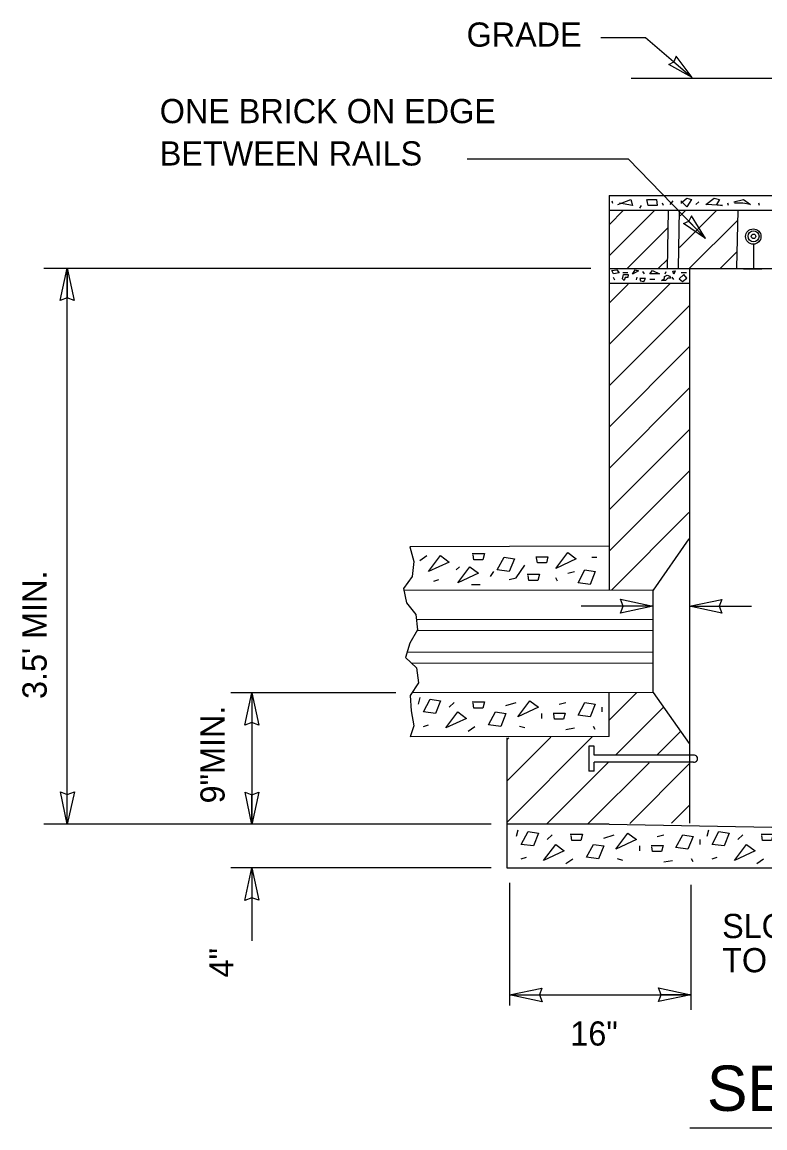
# Model space of a CAD drawing. Extents: x 19188 to 19495, y 20866 to 21061.
# Drawn here: x 19190.86 to 19216.59, y 20978.71 to 21017 of the extents above; entities that cross this region are included whole.
import ezdxf

# ---------------------------------------------------------------- set-up
doc = ezdxf.new("R2010")
doc.units = 0
doc.layers.add('G-ANNO-NOTE', color=7, linetype='Continuous')

msp = doc.modelspace()

# ---------------------------------------------------------------- linework, layer by layer
at = {"layer": 'G-ANNO-NOTE'}
for p, q in [((19220.92, 21015.045), (19211.963, 21015.045)), ((19211.192, 21010.995), (19211.192, 20997.329)), ((19211.192, 21010.995), (19217.267, 21010.995)), ((19211.192, 21010.489), (19242.647, 21010.489)), ((19211.192, 21008.907), (19212.774, 21010.489)), ((19211.192, 21009.981), (19211.699, 21010.489)), ((19213.217, 21008.464), (19213.257, 21010.48)), ((19213.598, 21008.492), (19213.637, 21010.482)), ((19214.921, 21010.489), (19213.63, 21009.197)), ((19213.848, 21010.489), (19213.651, 21010.292)), ((19215.623, 21008.493), (19215.663, 21010.476)), ((19211.823, 21008.464), (19213.233, 21009.874)), ((19213.97, 21008.464), (19215.65, 21010.143)), ((19216.198, 21009.31), (19216.198, 21008.487)), ((19212.896, 21008.464), (19213.224, 21008.792)), ((19215.044, 21008.464), (19215.621, 21009.04)), ((19210.566, 21008.464), (19191.621, 21008.464)), ((19192.426, 20989.226), (19192.426, 21008.477)), ((19192.426, 21008.477), (19192.426, 21007.446)), ((19211.192, 21008.464), (19242.647, 21008.464)), ((19211.293, 21008.401), (19211.465, 21008.418)), ((19211.344, 21008.286), (19211.293, 21008.401)), ((19211.546, 21008.319), (19211.344, 21008.286)), ((19211.465, 21008.418), (19211.546, 21008.319)), ((19211.668, 21008.332), (19211.846, 21008.332)), ((19212.003, 21008.269), (19212.095, 21008.418)), ((19212.216, 21008.385), (19212.003, 21008.269)), ((19212.095, 21008.418), (19212.216, 21008.385)), ((19212.611, 21008.286), (19212.693, 21008.401)), ((19212.693, 21008.401), (19212.946, 21008.286)), ((19213.402, 21008.369), (19213.483, 21008.385)), ((19213.433, 21008.269), (19213.402, 21008.369)), ((19213.483, 21008.385), (19213.433, 21008.269)), ((19213.696, 21008.332), (19213.874, 21008.332)), ((19213.976, 21008.464), (19213.976, 20989.265)), ((19215.848, 21008.459), (19216.485, 21008.459)), ((19211.192, 21007.957), (19213.976, 21007.957)), ((19211.192, 21005.837), (19213.304, 21007.948)), ((19211.192, 21007.269), (19211.852, 21007.928)), ((19211.658, 21008.103), (19211.689, 21008.252)), ((19211.719, 21008.054), (19211.658, 21008.103)), ((19211.689, 21008.252), (19211.851, 21008.252)), ((19211.749, 21008.153), (19211.719, 21008.054)), ((19211.841, 21008.153), (19211.749, 21008.153)), ((19211.851, 21008.252), (19211.841, 21008.153)), ((19212.459, 21008.12), (19212.257, 21008.12)), ((19212.257, 21008.12), (19212.277, 21008.037)), ((19212.277, 21008.037), (19212.399, 21008.02)), ((19212.399, 21008.02), (19212.459, 21008.12)), ((19212.601, 21008.099), (19212.779, 21008.099)), ((19212.946, 21008.286), (19212.611, 21008.286)), ((19213.007, 21008.054), (19213.108, 21008.12)), ((19213.098, 21008.054), (19213.007, 21008.054)), ((19213.149, 21008.054), (19213.098, 21008.054)), ((19213.108, 21008.12), (19213.118, 21008.186)), ((19213.118, 21008.186), (19213.21, 21008.236)), ((19213.23, 21008.136), (19213.149, 21008.054)), ((19213.21, 21008.236), (19213.301, 21008.203)), ((19213.321, 21008.136), (19213.23, 21008.136)), ((19213.301, 21008.203), (19213.321, 21008.136)), ((19213.787, 21008.252), (19213.625, 21008.103)), ((19213.625, 21008.103), (19213.737, 21008.02)), ((19213.737, 21008.02), (19213.889, 21008.136)), ((19213.889, 21008.136), (19213.787, 21008.252)), ((19211.192, 21004.405), (19213.974, 21007.187)), ((19211.192, 21002.973), (19213.972, 21005.753)), ((19211.192, 21001.541), (19213.969, 21004.318)), ((19211.192, 21000.109), (19213.967, 21002.884)), ((19211.192, 20998.677), (19213.964, 21001.449)), ((19211.276, 20997.329), (19213.962, 21000.015)), ((19211.192, 20998.845), (19204.29, 20998.833)), ((19213.96, 20999.103), (19212.718, 20997.329)), ((19204.643, 20998.357), (19204.88, 20998.523)), ((19204.94, 20997.971), (19205.357, 20998.523)), ((19205.357, 20998.523), (19205.654, 20998.302)), ((19207.321, 20998.026), (19207.559, 20998.468)), ((19207.559, 20998.468), (19207.916, 20998.413)), ((19207.916, 20998.413), (19207.737, 20997.971)), ((19209.344, 20998.081), (19209.761, 20998.633)), ((19210.059, 20998.413), (19209.344, 20998.081)), ((19209.761, 20998.633), (19210.059, 20998.413)), ((19210.594, 20998.468), (19210.773, 20998.468)), ((19205.654, 20998.302), (19204.94, 20997.971)), ((19205.892, 20998.026), (19206.011, 20998.136)), ((19205.952, 20997.584), (19206.368, 20998.136)), ((19206.368, 20998.136), (19206.666, 20997.915)), ((19207.082, 20997.805), (19207.202, 20997.971)), ((19207.737, 20997.971), (19207.321, 20998.026)), ((19207.975, 20997.749), (19208.273, 20998.191)), ((19209.761, 20997.915), (19209.999, 20997.971)), ((19210.118, 20997.584), (19210.356, 20998.026)), ((19210.356, 20998.026), (19210.714, 20997.971)), ((19210.714, 20997.971), (19210.535, 20997.529)), ((19205.119, 20997.639), (19205.297, 20997.695)), ((19206.666, 20997.915), (19205.952, 20997.584)), ((19207.737, 20997.695), (19207.975, 20997.749)), ((19209.404, 20997.639), (19209.344, 20997.749)), ((19210.535, 20997.529), (19210.118, 20997.584)), ((19212.718, 20997.329), (19204.109, 20997.314)), ((19206.428, 20997.529), (19206.726, 20997.529)), ((19212.707, 20997.329), (19212.744, 20997.366)), ((19212.711, 20997.329), (19212.711, 20993.785)), ((19212.711, 20996.772), (19210.23, 20996.772)), ((19212.711, 20996.772), (19211.681, 20996.772)), ((19213.976, 20996.772), (19216.126, 20996.772)), ((19213.976, 20996.772), (19215.007, 20996.772)), ((19212.72, 20996.316), (19204.558, 20996.303)), ((19212.693, 20995.936), (19204.559, 20995.923)), ((19212.694, 20995.177), (19204.217, 20995.163)), ((19212.693, 20994.797), (19204.377, 20994.784)), ((19203.809, 20993.771), (19198.097, 20993.771)), ((19198.821, 20993.771), (19198.821, 20989.213)), ((19198.821, 20993.771), (19198.821, 20992.741)), ((19212.725, 20993.785), (19204.379, 20993.771)), ((19211.192, 20992.264), (19211.192, 20993.785)), ((19211.192, 20992.824), (19212.154, 20993.785)), ((19212.725, 20993.785), (19213.972, 20992.015)), ((19204.643, 20993.606), (19204.583, 20993.385)), ((19204.761, 20993.109), (19204.999, 20993.551)), ((19204.999, 20993.551), (19205.357, 20993.496)), ((19205.357, 20993.496), (19205.178, 20993.054)), ((19205.833, 20993.441), (19205.654, 20993.275)), ((19207.618, 20993.33), (19207.975, 20993.441)), ((19208.035, 20992.943), (19208.451, 20993.496)), ((19208.451, 20993.496), (19208.749, 20993.275)), ((19209.463, 20993.385), (19209.701, 20993.441)), ((19210.118, 20992.999), (19210.356, 20993.441)), ((19210.356, 20993.441), (19210.714, 20993.385)), ((19210.714, 20993.385), (19210.535, 20992.943)), ((19205.178, 20993.054), (19204.761, 20993.109)), ((19205.535, 20992.557), (19205.952, 20993.109)), ((19205.952, 20993.109), (19206.25, 20992.888)), ((19207.023, 20992.667), (19207.261, 20993.109)), ((19207.261, 20993.109), (19207.618, 20993.054)), ((19207.618, 20993.054), (19207.44, 20992.612)), ((19208.749, 20993.275), (19208.035, 20992.943)), ((19208.868, 20992.888), (19208.868, 20993.054)), ((19210.535, 20992.943), (19210.118, 20992.999)), ((19210.952, 20993.109), (19210.952, 20993.275)), ((19213.075, 20993.274), (19211.441, 20991.64)), ((19204.761, 20992.612), (19204.94, 20992.667)), ((19206.25, 20992.888), (19205.535, 20992.557)), ((19206.309, 20992.446), (19206.547, 20992.612)), ((19207.44, 20992.612), (19207.023, 20992.667)), ((19208.273, 20992.557), (19208.095, 20992.612)), ((19210.713, 20992.502), (19210.654, 20992.612)), ((19211.192, 20992.264), (19204.301, 20992.252)), ((19207.649, 20989.28), (19210.624, 20992.256)), ((19207.649, 20990.712), (19209.172, 20992.236)), ((19207.649, 20992.144), (19207.72, 20992.215)), ((19207.649, 20992.214), (19207.649, 20989.226)), ((19209.701, 20992.502), (19209.999, 20992.557)), ((19213.67, 20992.438), (19212.869, 20991.637)), ((19210.676, 20991.926), (19210.488, 20991.926)), ((19210.488, 20991.926), (19210.488, 20991.059)), ((19210.676, 20991.619), (19210.676, 20991.926)), ((19214.117, 20991.619), (19210.676, 20991.619)), ((19209.035, 20989.235), (19211.16, 20991.36)), ((19210.475, 20989.244), (19212.581, 20991.349)), ((19214.122, 20991.366), (19210.676, 20991.366)), ((19210.676, 20991.059), (19210.676, 20991.366)), ((19211.916, 20989.252), (19213.973, 20991.309)), ((19210.676, 20991.059), (19210.488, 20991.059)), ((19192.426, 20989.226), (19192.426, 20990.257)), ((19198.821, 20989.213), (19198.821, 20990.244)), ((19213.357, 20989.261), (19213.976, 20989.879)), ((19207.107, 20989.226), (19191.621, 20989.226)), ((19211.192, 20989.226), (19207.649, 20989.226)), ((19207.649, 20989.226), (19207.649, 20987.708)), ((19211.192, 20989.226), (19240.021, 20988.692)), ((19208.035, 20989.021), (19207.975, 20988.8)), ((19208.154, 20988.524), (19208.392, 20988.966)), ((19208.392, 20988.966), (19208.749, 20988.911)), ((19208.749, 20988.911), (19208.571, 20988.469)), ((19209.225, 20988.855), (19209.047, 20988.69)), ((19211.011, 20988.745), (19211.368, 20988.855)), ((19211.428, 20988.358), (19211.844, 20988.911)), ((19211.844, 20988.911), (19212.142, 20988.69)), ((19212.856, 20988.8), (19213.094, 20988.855)), ((19213.511, 20988.413), (19213.749, 20988.855)), ((19213.749, 20988.855), (19214.106, 20988.8)), ((19214.106, 20988.8), (19213.927, 20988.358)), ((19214.642, 20989.021), (19214.582, 20988.8)), ((19214.761, 20988.524), (19214.999, 20988.966)), ((19214.999, 20988.966), (19215.356, 20988.911)), ((19215.356, 20988.911), (19215.177, 20988.469)), ((19215.832, 20988.855), (19215.653, 20988.69)), ((19208.571, 20988.469), (19208.154, 20988.524)), ((19208.927, 20987.971), (19209.344, 20988.524)), ((19209.344, 20988.524), (19209.642, 20988.303)), ((19210.416, 20988.082), (19210.654, 20988.524)), ((19210.654, 20988.524), (19211.011, 20988.469)), ((19211.011, 20988.469), (19210.832, 20988.027)), ((19212.142, 20988.69), (19211.428, 20988.358)), ((19212.261, 20988.303), (19212.261, 20988.469)), ((19213.927, 20988.358), (19213.511, 20988.413)), ((19214.344, 20988.524), (19214.344, 20988.69)), ((19215.177, 20988.469), (19214.761, 20988.524)), ((19215.534, 20987.971), (19215.951, 20988.524)), ((19215.951, 20988.524), (19216.249, 20988.303)), ((19208.154, 20988.027), (19208.333, 20988.082)), ((19209.642, 20988.303), (19208.927, 20987.971)), ((19209.701, 20987.861), (19209.94, 20988.027)), ((19210.832, 20988.027), (19210.416, 20988.082)), ((19211.666, 20987.971), (19211.487, 20988.027)), ((19214.106, 20987.916), (19214.047, 20988.027)), ((19214.761, 20988.027), (19214.939, 20988.082)), ((19216.249, 20988.303), (19215.534, 20987.971)), ((19216.308, 20987.861), (19216.546, 20988.027)), ((19207.107, 20987.708), (19198.097, 20987.708)), ((19198.821, 20987.708), (19198.821, 20985.181)), ((19198.821, 20987.708), (19198.821, 20986.677)), ((19207.649, 20987.708), (19249.414, 20987.708)), ((19213.094, 20987.916), (19213.391, 20987.971)), ((19207.75, 20987.197), (19207.75, 20982.941)), ((19214.025, 20987.123), (19214.025, 20982.792)), ((19207.75, 20983.315), (19214.025, 20983.314)), ((19207.75, 20983.315), (19208.781, 20983.315)), ((19214.025, 20983.314), (19212.995, 20983.314)), ((19213.987, 20978.708), (19246.848, 20978.708))]:
    msp.add_line(p, q, dxfattribs=at)
for points in [[(19210.913, 21016.468), (19212.452, 21016.468), (19214.067, 21015.083)], [(19206.275, 21012.261), (19211.855, 21012.261), (19214.535, 21009.509)], [(19211.292, 21010.811), (19211.318, 21010.726)], [(19211.502, 21010.683), (19211.947, 21010.853), (19212, 21010.641), (19211.555, 21010.726)], [(19212.262, 21010.556), (19212.315, 21010.641)], [(19212.524, 21010.853), (19212.839, 21010.853), (19212.865, 21010.641), (19212.55, 21010.641), (19212.498, 21010.853)], [(19213.075, 21010.641), (19213.049, 21010.726)], [(19213.31, 21010.683), (19213.416, 21010.811)], [(19213.678, 21010.726), (19213.887, 21010.896), (19214.045, 21010.853), (19213.887, 21010.598), (19213.678, 21010.811)], [(19214.202, 21010.683), (19214.307, 21010.768)], [(19214.543, 21010.683), (19214.831, 21010.896), (19215.015, 21010.853), (19214.91, 21010.683), (19215.119, 21010.641), (19214.569, 21010.683)], [(19215.329, 21010.641), (19215.303, 21010.726)], [(19215.513, 21010.768), (19215.854, 21010.853), (19216.09, 21010.683), (19215.827, 21010.726), (19215.539, 21010.726)], [(19216.404, 21010.641), (19216.378, 21010.726)], [(19192.426, 21007.446), (19192.18, 21007.356), (19192.426, 21008.477), (19192.661, 21007.358), (19192.426, 21007.446)], [(19212.419, 21008.279), (19212.367, 21008.364)], [(19213.142, 21008.275), (19213.168, 21008.36)], [(19211.395, 21008.063), (19211.343, 21008.148)], [(19212.139, 21008.076), (19212.165, 21008.162)], [(19213.433, 21008.08), (19213.381, 21008.165)], [(19204.29, 20998.833), (19204.433, 20998.323), (19204.379, 20997.797), (19204.074, 20997.388), (19204.182, 20996.891), (19204.505, 20996.481), (19204.559, 20995.955), (19204.289, 20995.488), (19204.146, 20994.991), (19204.523, 20994.64), (19204.595, 20994.114), (19204.307, 20993.676), (19204.343, 20993.15), (19204.433, 20992.624), (19204.301, 20992.252)], [(19206.456, 20998.595), (19206.875, 20998.595), (19206.823, 20998.383), (19206.509, 20998.383), (19206.483, 20998.553)], [(19208.658, 20998.485), (19209.078, 20998.485), (19209.026, 20998.272), (19208.711, 20998.272), (19208.684, 20998.442)], [(19208.361, 20997.877), (19208.78, 20997.877), (19208.728, 20997.664), (19208.414, 20997.664), (19208.387, 20997.835)], [(19211.68, 20996.772), (19211.59, 20997.018), (19212.711, 20996.772), (19211.592, 20996.536), (19211.68, 20996.772)], [(19215.007, 20996.772), (19215.098, 20996.525), (19213.976, 20996.772), (19215.095, 20997.007), (19215.007, 20996.772)], [(19198.821, 20992.74), (19198.575, 20992.65), (19198.821, 20993.771), (19199.057, 20992.652), (19198.821, 20992.74)], [(19206.456, 20993.458), (19206.875, 20993.458), (19206.823, 20993.245), (19206.509, 20993.245), (19206.483, 20993.416)], [(19209.254, 20993.071), (19209.673, 20993.071), (19209.62, 20992.858), (19209.306, 20992.858), (19209.28, 20993.029)], [(19192.426, 20990.257), (19192.672, 20990.347), (19192.426, 20989.226), (19192.191, 20990.345), (19192.426, 20990.257)], [(19198.821, 20990.244), (19199.068, 20990.334), (19198.821, 20989.213), (19198.586, 20990.332), (19198.821, 20990.244)], [(19209.849, 20988.873), (19210.268, 20988.873), (19210.216, 20988.66), (19209.901, 20988.66), (19209.875, 20988.83)], [(19216.456, 20988.873), (19216.875, 20988.873), (19216.822, 20988.66), (19216.508, 20988.66), (19216.482, 20988.83)], [(19212.646, 20988.486), (19213.066, 20988.486), (19213.013, 20988.273), (19212.698, 20988.273), (19212.672, 20988.443)], [(19198.821, 20986.677), (19198.575, 20986.586), (19198.821, 20987.708), (19199.057, 20986.589), (19198.821, 20986.677)], [(19208.781, 20983.315), (19208.872, 20983.068), (19207.75, 20983.315), (19208.869, 20983.55), (19208.781, 20983.315)], [(19212.994, 20983.314), (19212.904, 20983.561), (19214.025, 20983.314), (19212.906, 20983.079), (19212.994, 20983.314)]]:
    msp.add_lwpolyline(points, dxfattribs=at)
for points in [[(19213.514, 21015.817), (19213.441, 21015.62), (19214.067, 21015.083), (19213.265, 21015.523), (19213.441, 21015.62), (19214.067, 21015.083)], [(19214.051, 21010.289), (19213.96, 21010.099), (19214.535, 21009.509), (19213.776, 21010.018), (19213.96, 21010.099), (19214.535, 21009.509)]]:
    msp.add_lwpolyline(points, close=True, dxfattribs=at)
for centre, radius in [((19216.189, 21009.572), 0.266), ((19216.197, 21009.579), 0.19), ((19216.197, 21009.579), 0.0759)]:
    msp.add_circle(centre, radius, dxfattribs=at)
msp.add_arc((19214.13, 20991.493), 0.127, 266.522, 96.1025, dxfattribs=at)

# ---------------------------------------------------------------- texts
for s, height, p in [('GRADE', 0.8379, (19206.259, 21016.146)), ('ONE BRICK ON EDGE', 0.83785, (19195.63, 21013.497)), ('BETWEEN RAILS', 0.83785, (19195.63, 21012.031)), ('SLOPE FLOOR ', 0.83785, (19215.11, 20985.28)), ('TO DRAIN', 0.8379, (19215.11, 20984.097)), ('16"', 0.8379, (19209.852, 20981.558)), ('SECTION TYPE "S" HANDHOLE', 1.57098, (19214.585, 20979.297))]:
    msp.add_text(s, height=height, dxfattribs=at).set_placement(p)
for s, p in [("3.5' MIN.", (19191.713, 20993.559)), ('9"MIN.', (19197.877, 20989.942)), ('4"', (19198.183, 20983.916))]:
    msp.add_text(s, height=0.8379, rotation=90, dxfattribs=at).set_placement(p)

doc.saveas('drawing.dxf')
